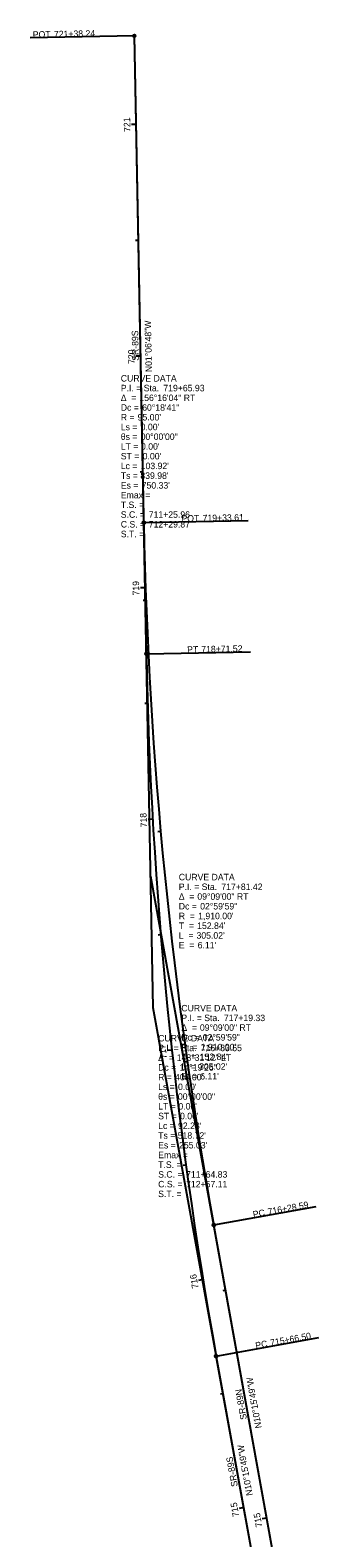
# Model space of a CAD drawing. Extents: x 2047151 to 2048731, y 456453 to 457874.
# Drawn here: x 2047569 to 2047694, y 457223 to 457874 of the extents above; entities that cross this region are included whole.
import ezdxf

# ---------------------------------------------------------------- set-up
doc = ezdxf.new("R2010")
doc.units = 0
for name, color, linetype in [('GE_P_Alignment', 7, 'Continuous'), ('GE_P_Alignment_100_Bearings', 7, 'Continuous'), ('GE_P_Alignment_100_Cardinal_Points', 7, 'Continuous'), ('GE_P_Alignment_100_Curve_Data', 7, 'Continuous'), ('GE_P_Alignment_100_Distances', 7, 'Continuous'), ('GE_P_Alignment_100_Stations', 7, 'Continuous'), ('GE_P_Alignment_500_Bearings', 7, 'Continuous'), ('GE_P_Alignment_500_Cardinal_Points', 7, 'Continuous'), ('GE_P_Alignment_500_Curve_Data', 7, 'Continuous'), ('GE_P_Alignment_500_Distances', 7, 'Continuous'), ('GE_P_Alignment_500_Stations', 7, 'Continuous')]:
    doc.layers.add(name, color=color, linetype=linetype)

msp = doc.modelspace()

# ---------------------------------------------------------------- linework, layer by layer
at = {"layer": 'GE_P_Alignment'}
for p, q in [((2047622.24, 457451.67), (2047614.08, 457871.15)), ((2047619.27, 457604.48), (2047614.08, 457871.15)), ((2047679.37, 457186.67), (2047621.14, 457508.26)), ((2047680.68, 457128.93), (2047622.24, 457451.67)), ((2047676.14, 457204.48), (2047648.37, 457357.87)), ((2047667.29, 457202.88), (2047649.47, 457301.28))]:
    msp.add_line(p, q, dxfattribs=at)
for centre in [(2049527.81, 457698.18), (2049527.81, 457698.18), (2049528.91, 457641.59), (2049528.91, 457641.59)]:
    msp.add_arc(centre, 1910, 181.11347, 190.26352, dxfattribs=at)
at = {"layer": 'GE_P_Alignment_100_Cardinal_Points'}
for p, q in [((2047614.08, 457871.15), (2047569.09, 457870.28)), ((2047619.27, 457604.48), (2047664.26, 457605.35)), ((2047649.47, 457301.28), (2047693.75, 457309.3))]:
    msp.add_line(p, q, dxfattribs=at)
for centre in [(2047614.08, 457871.15), (2047619.27, 457604.48), (2047649.47, 457301.28)]:
    msp.add_circle(centre, 0.6, dxfattribs=at)
at = {"layer": 'GE_P_Alignment_100_Stations'}
for p, q in [((2047614.83, 457832.92), (2047612.83, 457832.88)), ((2047615.8, 457782.92), (2047614.6, 457782.9)), ((2047616.77, 457732.93), (2047614.77, 457732.9)), ((2047617.74, 457682.94), (2047616.54, 457682.92)), ((2047618.71, 457632.95), (2047616.71, 457632.91)), ((2047619.81, 457582.97), (2047618.61, 457582.93)), ((2047622, 457533.01), (2047620, 457532.9)), ((2047625.49, 457483.14), (2047624.3, 457483.04)), ((2047630.29, 457433.37), (2047628.3, 457433.15)), ((2047636.39, 457383.75), (2047635.2, 457383.58)), ((2047643.79, 457334.3), (2047641.82, 457333.98)), ((2047652.41, 457285.05), (2047651.23, 457284.83)), ((2047661.32, 457235.85), (2047659.35, 457235.49))]:
    msp.add_line(p, q, dxfattribs=at)
at = {"layer": 'GE_P_Alignment_500_Cardinal_Points'}
for p, q in [((2047618.17, 457661.06), (2047663.16, 457661.94)), ((2047648.37, 457357.87), (2047692.65, 457365.88))]:
    msp.add_line(p, q, dxfattribs=at)
for centre in [(2047618.17, 457661.06), (2047648.37, 457357.87)]:
    msp.add_circle(centre, 0.6, dxfattribs=at)
at = {"layer": 'GE_P_Alignment_500_Stations'}
for p, q in [((2047619.12, 457627.47), (2047617.92, 457627.42)), ((2047625.43, 457527.68), (2047624.24, 457527.57)), ((2047636.96, 457428.36), (2047635.77, 457428.19)), ((2047653.46, 457329.74), (2047652.28, 457329.52)), ((2047671.28, 457231.34), (2047669.31, 457230.98))]:
    msp.add_line(p, q, dxfattribs=at)

# ---------------------------------------------------------------- texts
at = {"layer": 'GE_P_Alignment_100_Bearings'}
for s, rotation, p in [('N01°06\'48"W', 91.11347, (2047621.71, 457726.05)), ('N10°15\'49"W', 100.26352, (2047665.22, 457241.26))]:
    msp.add_text(s, height=2.8, rotation=rotation, dxfattribs=at).set_placement(p)
at = {"layer": 'GE_P_Alignment_100_Cardinal_Points'}
for s, rotation, p in [('POT', 1.11347, (2047570.25, 457870.35)), ('721+38.24', 1.11347, (2047579.38, 457870.53)), ('PT', 1.11347, (2047636.91, 457604.87)), ('718+71.52', 1.11347, (2047643, 457604.99)), ('PC', 10.26352, (2047666.61, 457304.43)), ('715+66.50', 10.26352, (2047673.02, 457305.59))]:
    msp.add_text(s, height=2.8, rotation=rotation, dxfattribs=at).set_placement(p)
at = {"layer": 'GE_P_Alignment_100_Curve_Data'}
for s, p in [('CURVE DATA', (2047634.37, 457450.08)), ('Δ  = ', (2047634.37, 457441.68)), ('P.I. = Sta. ', (2047634.37, 457445.88)), ('09°09\'00" RT', (2047642.39, 457441.68)), ('717+19.33', (2047652.74, 457445.88)), ('CURVE DATA', (2047624.37, 457437.11)), ('Dc = ', (2047634.37, 457437.48)), ('02°59\'59"', (2047643.61, 457437.48)), ('Δ  = ', (2047624.37, 457428.71)), ('P.I. = Sta. ', (2047624.37, 457432.91)), ('148°31\'12" LT', (2047632.39, 457428.71)), ('T  = ', (2047634.37, 457429.08)), ('R  = ', (2047634.37, 457433.28)), ("152.84'", (2047642.3, 457429.08)), ('716+83.55', (2047642.73, 457432.91)), ("1,910.00'", (2047642.74, 457433.28)), ('Dc = ', (2047624.37, 457424.51)), ('14°19\'26"', (2047633.61, 457424.51)), ('L  = ', (2047634.37, 457424.88)), ("305.02'", (2047642.02, 457424.88)), ('R = ', (2047624.37, 457420.31)), ('Ls = ', (2047624.37, 457416.11)), ("400.00'", (2047631.65, 457420.31)), ("0.00'", (2047632.95, 457416.11)), ('E  = ', (2047634.37, 457420.68)), ("6.11'", (2047642.52, 457420.68)), ('θs = ', (2047624.37, 457411.91)), ('00°00\'00"', (2047632.9, 457411.91)), ('ST = ', (2047624.37, 457403.51)), ('LT = ', (2047624.37, 457407.71)), ("0.00'", (2047633.1, 457407.71)), ("0.00'", (2047633.82, 457403.51)), ('Lc = ', (2047624.37, 457399.31)), ("92.28'", (2047632.95, 457399.31)), ('Ts = ', (2047624.37, 457395.11)), ('Es = ', (2047624.37, 457390.91)), ("518.72'", (2047632.81, 457395.11)), ("255.03'", (2047633.39, 457390.91)), ('Emax = ', (2047624.37, 457386.71)), ('T.S. = ', (2047624.37, 457382.51)), ('S.C. = ', (2047624.37, 457378.31)), ('711+64.83', (2047636.43, 457378.31)), ('C.S. = ', (2047624.37, 457374.11)), ('712+57.11', (2047636.43, 457374.11)), ('S.T. = ', (2047624.37, 457369.91))]:
    msp.add_text(s, height=2.8, dxfattribs=at).set_placement(p)
at = {"layer": 'GE_P_Alignment_100_Distances'}
for rotation, p in [(91.11347, (2047615.99, 457730.94)), (100.26352, (2047658.79, 457245.19))]:
    msp.add_text('SR-89S', height=2.8, rotation=rotation, dxfattribs=at).set_placement(p)
at = {"layer": 'GE_P_Alignment_100_Stations'}
for s, rotation, p in [('721', 91.11347, (2047612.39, 457829.76)), ('720', 91.11347, (2047614.29, 457729.61)), ('719', 91.11347, (2047616.23, 457629.65)), ('718', 93.25893, (2047619.64, 457529.6)), ('717', 96.25871, (2047628.17, 457429.78)), ('716', 99.25849, (2047641.8, 457330.65)), ('715', 100.26352, (2047659.4, 457232.15))]:
    msp.add_text(s, height=2.8, rotation=rotation, dxfattribs=at).set_placement(p)
at = {"layer": 'GE_P_Alignment_500_Bearings'}
msp.add_text('N10°15\'49"W', height=2.8, rotation=100.26352, dxfattribs=at).set_placement((2047669.09, 457270.35))
at = {"layer": 'GE_P_Alignment_500_Cardinal_Points'}
for s, rotation, p in [('POT', 1.11347, (2047634.45, 457661.43)), ('719+33.61', 1.11347, (2047643.58, 457661.61)), ('716+28.59', 10.26352, (2047671.95, 457362.18)), ('PC', 10.26352, (2047665.53, 457361.02))]:
    msp.add_text(s, height=2.8, rotation=rotation, dxfattribs=at).set_placement(p)
at = {"layer": 'GE_P_Alignment_500_Curve_Data'}
for s, p in [('CURVE DATA', (2047608.23, 457721.96)), ('P.I. = Sta. ', (2047608.23, 457717.76)), ('719+65.93', (2047626.6, 457717.76)), ('Δ  = ', (2047608.23, 457713.56)), ('Dc = ', (2047608.23, 457709.36)), ('156°16\'04" RT', (2047616.25, 457713.56)), ('60°18\'41"', (2047617.47, 457709.36)), ('R = ', (2047608.23, 457705.16)), ("95.00'", (2047615.51, 457705.16)), ('θs = ', (2047608.23, 457696.76)), ('Ls = ', (2047608.23, 457700.96)), ('00°00\'00"', (2047616.77, 457696.76)), ("0.00'", (2047616.82, 457700.96)), ('LT = ', (2047608.23, 457692.56)), ("0.00'", (2047616.96, 457692.56)), ('ST = ', (2047608.23, 457688.36)), ('Lc = ', (2047608.23, 457684.16)), ("103.92'", (2047616.82, 457684.16)), ("0.00'", (2047617.69, 457688.36)), ('Ts = ', (2047608.23, 457679.96)), ("839.98'", (2047616.68, 457679.96)), ('Es = ', (2047608.23, 457675.76)), ('Emax = ', (2047608.23, 457671.56)), ("750.33'", (2047617.26, 457675.76)), ('T.S. = ', (2047608.23, 457667.36)), ('S.C. = ', (2047608.23, 457663.16)), ('711+25.96', (2047620.3, 457663.16)), ('C.S. = ', (2047608.23, 457658.96)), ('712+29.87', (2047620.3, 457658.96)), ('S.T. = ', (2047608.23, 457654.76)), ('CURVE DATA', (2047633.27, 457506.67)), ('P.I. = Sta. ', (2047633.27, 457502.47)), ('717+81.42', (2047651.64, 457502.47)), ('Δ  = ', (2047633.27, 457498.27)), ('Dc = ', (2047633.27, 457494.07)), ('09°09\'00" RT', (2047641.29, 457498.27)), ('02°59\'59"', (2047642.51, 457494.07)), ('R  = ', (2047633.27, 457489.87)), ("1,910.00'", (2047641.64, 457489.87)), ('T  = ', (2047633.27, 457485.67)), ('L  = ', (2047633.27, 457481.47)), ("305.02'", (2047640.92, 457481.47)), ("152.84'", (2047641.2, 457485.67)), ('E  = ', (2047633.27, 457477.27)), ("6.11'", (2047641.42, 457477.27))]:
    msp.add_text(s, height=2.8, dxfattribs=at).set_placement(p)
at = {"layer": 'GE_P_Alignment_500_Distances'}
msp.add_text('SR-89N', height=2.8, rotation=100.26352, dxfattribs=at).set_placement((2047662.7, 457274.12))
at = {"layer": 'GE_P_Alignment_500_Stations'}
msp.add_text('715', height=2.8, rotation=100.26352, dxfattribs=at).set_placement((2047669.36, 457227.64))

doc.saveas('drawing.dxf')
